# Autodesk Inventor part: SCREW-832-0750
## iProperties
Created: 2007-08
Part Number: SCREW-832-0750
Material: Stainless Steel
Document SubType Name: Modeling
Density: 8.08 g/cm^3
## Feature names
1. Base1
